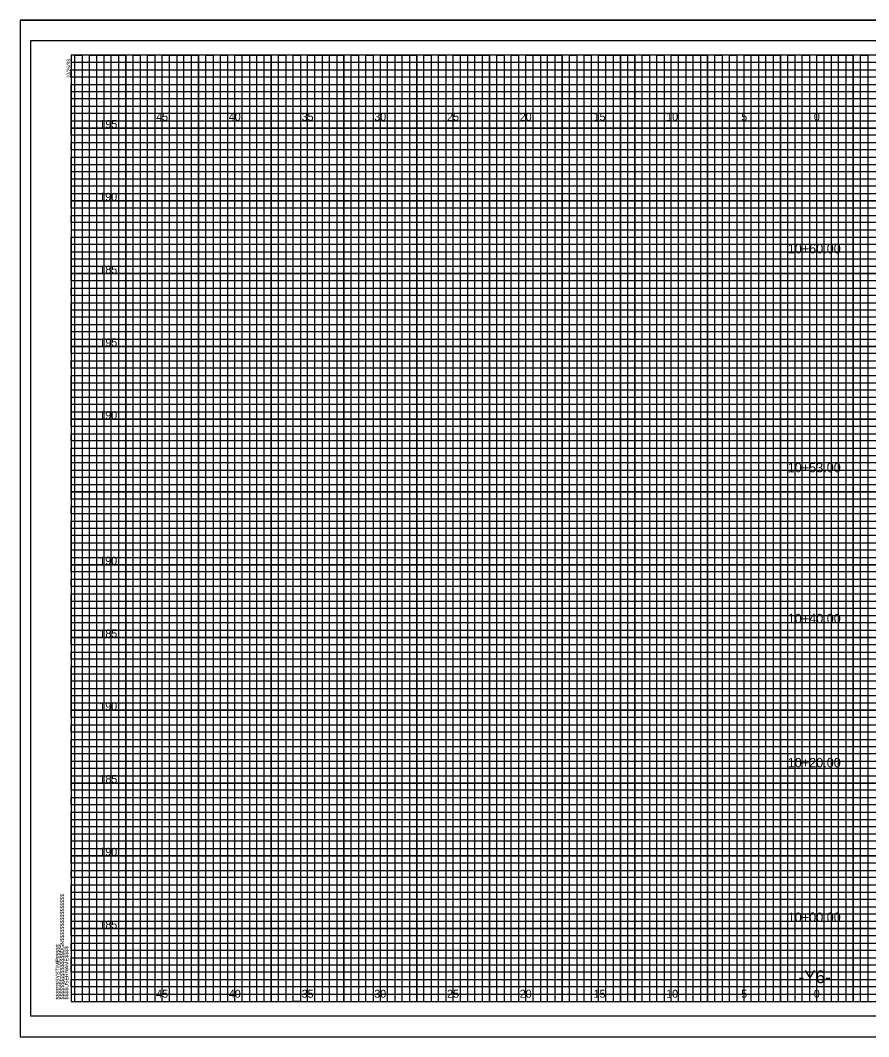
# Model space of a CAD drawing. Extents: x -4 to 103, y -2 to 138.
# Drawn here: x -3.5 to 54.8, y -2.4 to 67.4 of the extents above; entities that cross this region are included whole.
import ezdxf

# ---------------------------------------------------------------- set-up
doc = ezdxf.new("R2010")
doc.units = 0
for name, color, linetype in [('Old_Level_10', 7, 'Continuous'), ('Old_Level_16', 7, 'Continuous'), ('Old_Level_3', 7, 'Continuous'), ('Old_Level_4', 7, 'Continuous'), ('Old_Level_5', 7, 'Continuous'), ('Old_Level_8', 7, 'Continuous'), ('Prop Dimension', 7, 'Continuous'), ('Prop XS Dump Level', 7, 'Continuous'), ('Prop XS Finish Grade', 7, 'Continuous'), ('Prop XS SE Text', 7, 'Continuous'), ('Prop XS Subgrade Earthwork', 7, 'Continuous')]:
    doc.layers.add(name, color=color, linetype=linetype)

msp = doc.modelspace()

# ---------------------------------------------------------------- linework, layer by layer
at = {"layer": 'Old_Level_10'}
for p, q in [((1.25, 0), (1.25, 65)), ((3.75, 0), (3.75, 65)), ((6.25, 0), (6.25, 65)), ((8.75, 0), (8.75, 65)), ((11.25, 0), (11.25, 65)), ((13.75, 0), (13.75, 65)), ((16.25, 0), (16.25, 65)), ((18.75, 0), (18.75, 65)), ((21.25, 0), (21.25, 65)), ((23.75, 0), (23.75, 65)), ((26.25, 0), (26.25, 65)), ((28.75, 0), (28.75, 65)), ((31.25, 0), (31.25, 65)), ((33.75, 0), (33.75, 65)), ((36.25, 0), (36.25, 65)), ((38.75, 0), (38.75, 65)), ((41.25, 0), (41.25, 65)), ((43.75, 0), (43.75, 65)), ((46.25, 0), (46.25, 65)), ((48.75, 0), (48.75, 65)), ((51.25, 0), (51.25, 65)), ((53.75, 0), (53.75, 65)), ((0, 62.5), (74.25, 62.5)), ((0, 60), (102.5, 60)), ((0, 57.5), (102.5, 57.5)), ((0, 55), (102.5, 55)), ((0, 52.5), (102.5, 52.5)), ((0, 50), (102.5, 50)), ((0, 47.5), (102.5, 47.5)), ((0, 45), (102.5, 45)), ((0, 42.5), (102.5, 42.5)), ((0, 40), (102.5, 40)), ((0, 37.5), (102.5, 37.5)), ((0, 35), (102.5, 35)), ((0, 32.5), (102.5, 32.5)), ((0, 30), (102.5, 30)), ((0, 27.5), (102.5, 27.5)), ((0, 25), (102.5, 25)), ((0, 22.5), (102.5, 22.5)), ((0, 20), (102.5, 20)), ((0, 17.5), (102.5, 17.5)), ((0, 15), (102.5, 15)), ((0, 12.5), (102.5, 12.5)), ((0, 10), (102.5, 10)), ((0, 7.5), (102.5, 7.5)), ((0, 5), (102.5, 5)), ((0, 2.5), (102.5, 2.5))]:
    msp.add_line(p, q, dxfattribs=at)
at = {"layer": 'Old_Level_3'}
for p, q in [((-3.5, 67.4), (103.4, 67.4)), ((-3.5, 67.4), (-3.5, -2.425)), ((-3.5, -2.425), (102.1625, -2.425))]:
    msp.add_line(p, q, dxfattribs=at)
at = {"layer": 'Old_Level_4'}
msp.add_lwpolyline([(103, 66), (-2.8, 66), (-2.8, -1), (103, -1)], close=True, dxfattribs=at)
at = {"layer": 'Old_Level_5'}
msp.add_lwpolyline([(103.4, 67.4), (-3.5, 67.4), (-3.5, -2.425), (103.4, -2.425)], close=True, dxfattribs=at)
at = {"layer": 'Old_Level_8'}
for points in [[(1.25, 0), (1.25, 65), (3.75, 65), (3.75, 0), (6.25, 0), (6.25, 65), (8.75, 65), (8.75, 0), (11.25, 0), (11.25, 65), (13.75, 65), (13.75, 0), (16.25, 0), (16.25, 65), (18.75, 65), (18.75, 0), (21.25, 0), (21.25, 65), (23.75, 65), (23.75, 0), (26.25, 0), (26.25, 65), (28.75, 65), (28.75, 0), (31.25, 0), (31.25, 65), (33.75, 65), (33.75, 0), (36.25, 0), (36.25, 65), (38.75, 65), (38.75, 0), (41.25, 0), (41.25, 65), (43.75, 65), (43.75, 0), (46.25, 0), (46.25, 65), (48.75, 65), (48.75, 0), (51.25, 0), (51.25, 65), (53.75, 65), (53.75, 0)], [(102.5, 60), (0, 60), (0, 62.5), (74.25, 62.5)], [(102.5, 55), (0, 55), (0, 57.5), (102.5, 57.5)], [(102.5, 50), (0, 50), (0, 52.5), (102.5, 52.5)], [(102.5, 45), (0, 45), (0, 47.5), (102.5, 47.5)], [(102.5, 40), (0, 40), (0, 42.5), (102.5, 42.5)], [(102.5, 35), (0, 35), (0, 37.5), (102.5, 37.5)], [(102.5, 30), (0, 30), (0, 32.5), (102.5, 32.5)], [(102.5, 25), (0, 25), (0, 27.5), (102.5, 27.5)], [(102.5, 20), (0, 20), (0, 22.5), (102.5, 22.5)], [(102.5, 15), (0, 15), (0, 17.5), (102.5, 17.5)], [(102.5, 10), (0, 10), (0, 12.5), (102.5, 12.5)], [(102.5, 5), (0, 5), (0, 7.5), (102.5, 7.5)], [(0, 2.5), (102.5, 2.5)]]:
    msp.add_lwpolyline(points, dxfattribs=at)
at = {"layer": 'Prop Dimension'}
for points in [[(0.25, 0), (0.25, 65), (0.75, 65), (0.75, 0), (1.75, 0), (1.75, 65), (2.25, 65), (2.25, 0), (2.75, 0), (2.75, 65), (3.25, 65), (3.25, 0), (4.25, 0), (4.25, 65), (4.75, 65), (4.75, 0), (5.25, 0), (5.25, 65), (5.75, 65), (5.75, 0), (6.75, 0), (6.75, 65), (7.25, 65), (7.25, 0), (7.75, 0), (7.75, 65), (8.25, 65), (8.25, 0), (9.25, 0), (9.25, 65), (9.75, 65), (9.75, 0), (10.25, 0), (10.25, 65), (10.75, 65), (10.75, 0), (11.75, 0), (11.75, 65), (12.25, 65), (12.25, 0), (12.75, 0), (12.75, 65), (13.25, 65), (13.25, 0), (14.25, 0), (14.25, 65), (14.75, 65), (14.75, 0), (15.75, 0), (15.25, 0), (15.25, 65), (15.75, 65), (15.75, 0), (16.75, 0), (16.75, 65), (17.25, 65), (17.25, 0), (17.75, 0), (17.75, 65), (18.25, 65), (18.25, 0), (19.25, 0), (19.25, 65), (19.75, 65), (19.75, 0), (20.25, 0), (20.25, 65), (20.75, 65), (20.75, 0), (21.75, 0), (21.75, 65), (22.25, 65), (22.25, 0), (22.75, 0), (22.75, 65), (23.25, 65), (23.25, 0), (24.25, 0), (24.25, 65), (24.75, 65), (24.75, 0), (25.25, 0), (25.25, 65), (25.75, 65), (25.75, 0), (26.75, 0), (26.75, 65), (27.25, 65), (27.25, 0), (27.75, 0), (27.75, 65), (28.25, 65), (28.25, 0), (29.25, 0), (29.25, 65), (29.75, 65), (29.75, 0), (30.25, 0), (30.25, 65), (30.75, 65), (30.75, 0)], [(30.75, 0), (31.75, 0), (31.75, 65), (32.25, 65), (32.25, 0), (32.75, 0), (32.75, 65), (33.25, 65), (33.25, 0), (34.25, 0), (34.25, 65), (34.75, 65), (34.75, 0), (35.25, 0), (35.25, 65), (35.75, 65), (35.75, 0), (36.75, 0), (36.75, 65), (37.25, 65), (37.25, 0), (37.75, 0), (37.75, 65), (37.75, 0)], [(38.25, 65), (38.25, 0), (39.25, 0), (39.25, 65), (39.75, 65), (39.75, 0), (40.25, 0), (40.25, 65), (40.75, 65), (40.75, 0), (41.75, 0), (41.75, 65), (42.25, 65), (42.25, 0), (42.75, 0), (42.75, 65), (43.25, 65), (43.25, 0), (43.75, 0), (44.25, 0), (44.25, 65), (44.75, 65), (44.75, 0), (45.25, 0), (45.25, 65), (45.75, 65), (45.75, 0), (46.75, 0), (46.75, 65), (47.25, 65), (47.25, 0), (47.75, 0), (47.75, 65), (48.25, 65), (48.25, 0), (49.25, 0), (49.25, 65), (49.75, 65), (49.75, 0), (50.25, 0), (50.25, 65), (50.75, 65), (50.75, 0), (51.75, 0), (51.75, 65), (52.25, 65), (52.25, 0), (52.75, 0), (52.75, 65), (53.25, 65), (53.25, 0), (54.25, 0), (54.25, 65), (54.75, 65), (54.75, 0), (55.25, 0)], [(0, 62), (0, 63), (74.25, 63), (74.25, 63.5), (0, 63.5), (0, 64), (74.25, 64), (74.25, 64.5), (0, 64.5)], [(102.5, 62), (0, 62)], [(102.5, 61), (0, 61), (0, 61.5), (102.5, 61.5)], [(102.5, 59.5), (0, 59.5), (0, 60.5), (102.5, 60.5)], [(102.5, 58.5), (0, 58.5), (0, 59), (102.5, 59)], [(102.5, 57), (0, 57), (0, 58), (102.5, 58)], [(102.5, 56), (0, 56), (0, 56.5), (102.5, 56.5)], [(102.5, 54.5), (0, 54.5), (0, 55.5), (102.5, 55.5)], [(102.5, 53.5), (0, 53.5), (0, 54), (102.5, 54)], [(0, 53), (102.5, 53)], [(102.5, 52), (0, 52)], [(102.5, 51), (0, 51), (0, 51.5), (102.5, 51.5)], [(102.5, 49.5), (0, 49.5), (0, 50.5), (102.5, 50.5)], [(102.5, 48.5), (0, 48.5), (0, 49), (102.5, 49)], [(102.5, 47), (0, 47), (0, 48), (102.5, 48)], [(102.5, 46), (0, 46), (0, 46.5), (102.5, 46.5)], [(102.5, 44.5), (0, 44.5), (0, 45.5), (102.5, 45.5)], [(102.5, 43.5), (0, 43.5), (0, 44), (102.5, 44)], [(102.5, 42), (0, 42), (0, 43), (102.5, 43)], [(102.5, 41), (0, 41), (0, 41.5), (102.5, 41.5)], [(102.5, 39.5), (0, 39.5), (0, 40.5), (102.5, 40.5)], [(102.5, 38.5), (0, 38.5), (0, 39), (102.5, 39)], [(102.5, 37), (0, 37), (0, 38), (102.5, 38)], [(102.5, 36), (0, 36), (0, 36.5), (102.5, 36.5)], [(102.5, 34.5), (0, 34.5), (0, 35.5), (102.5, 35.5)], [(102.5, 33.5), (0, 33.5), (0, 34), (102.5, 34)], [(102.5, 32), (0, 32), (0, 33), (102.5, 33)], [(102.5, 31), (0, 31), (0, 31.5)], [(0, 31.5), (102.5, 31.5)], [(102.5, 29.5), (0, 29.5), (0, 30.5), (102.5, 30.5)], [(102.5, 28.5), (0, 28.5), (0, 29), (102.5, 29)], [(102.5, 27), (0, 27), (0, 28), (102.5, 28)], [(102.5, 26), (0, 26), (0, 26.5), (102.5, 26.5)], [(102.5, 24.5), (0, 24.5), (0, 25.5), (102.5, 25.5)], [(102.5, 23.5), (0, 23.5), (0, 24), (102.5, 24)], [(102.5, 22), (0, 22), (0, 23), (102.5, 23)], [(102.5, 21), (0, 21), (0, 21.5), (102.5, 21.5)], [(102.5, 19.5), (0, 19.5), (0, 20.5), (102.5, 20.5)], [(102.5, 18.5), (0, 18.5), (0, 19), (102.5, 19)], [(102.5, 17), (0, 17), (0, 18), (102.5, 18)], [(102.5, 16), (0, 16), (0, 16.5), (102.5, 16.5)], [(102.5, 14.5), (0, 14.5), (0, 15.5), (102.5, 15.5)], [(102.5, 13.5), (0, 13.5), (0, 14), (102.5, 14)], [(102.5, 12), (0, 12), (0, 13), (102.5, 13)], [(102.5, 11), (0, 11), (0, 11.5), (102.5, 11.5)], [(102.5, 9.5), (0, 9.5), (0, 10.5), (102.5, 10.5)], [(102.5, 8.5), (0, 8.5), (0, 9), (102.5, 9)], [(102.5, 7), (0, 7), (0, 8), (102.5, 8)], [(102.5, 6), (0, 6), (0, 6.5), (102.5, 6.5)], [(102.5, 4.5), (0, 4.5), (0, 5.5), (102.5, 5.5)], [(102.5, 3.5), (0, 3.5), (0, 4), (102.5, 4)], [(102.5, 2), (0, 2), (0, 3), (102.5, 3)], [(102.5, 1), (0, 1), (0, 1.5), (102.5, 1.5)], [(0, 0.5), (102.5, 0.5)]]:
    msp.add_lwpolyline(points, dxfattribs=at)
at = {"layer": 'Prop XS SE Text'}
for p, q in [((0, 0), (0, 0)), ((0, 0), (0, 0)), ((-3.5, -2.425), (103.4, -2.425))]:
    msp.add_line(p, q, dxfattribs=at)
msp.add_lwpolyline([(102.5, 65), (0, 65), (0, 0), (102.5, 0)], close=True, dxfattribs=at)

# ---------------------------------------------------------------- texts
at = {"layer": 'Old_Level_16'}
for s, p in [('45', (5.8399, 60.5)), ('40', (10.8313, 60.5)), ('35', (15.8399, 60.5)), ('30', (20.8313, 60.5)), ('25', (25.8399, 60.5)), ('20', (30.8313, 60.5)), ('15', (35.9058, 60.5)), ('10', (40.8971, 60.5)), ('5', (46.0574, 60.5)), ('0', (51.0488, 60.5)), ('0', (51.0488, 60.5)), ('45', (5.8399, 0.25)), ('40', (10.8313, 0.25)), ('35', (15.8399, 0.25)), ('30', (20.8313, 0.25)), ('25', (25.8399, 0.25)), ('20', (30.8313, 0.25)), ('15', (35.9058, 0.25)), ('10', (40.8971, 0.25)), ('5', (46.0574, 0.25)), ('0', (51.0488, 0.25)), ('0', (51.0488, 0.25))]:
    msp.add_text(s, height=0.55, dxfattribs=at).set_placement(p)
at = {"layer": 'Old_Level_8'}
msp.add_text('040397', height=0.0025, rotation=90, dxfattribs=at).set_placement((-0.0007, 64.9864))
at = {"layer": 'Prop XS Dump Level'}
msp.add_text('-Y6-', height=0.875, dxfattribs=at).set_placement((49.9985, 1.25))
at = {"layer": 'Prop XS Finish Grade'}
for s, p in [('195', (1.9383, 60)), ('190', (1.9296, 55)), ('185', (1.9383, 50)), ('195', (1.9383, 45)), ('190', (1.9296, 40)), ('190', (1.9296, 30)), ('185', (1.9383, 25)), ('190', (1.9296, 20)), ('185', (1.9383, 15)), ('190', (1.9296, 10)), ('185', (1.9383, 5))]:
    msp.add_text(s, height=0.55, dxfattribs=at).set_placement(p)
at = {"layer": 'Prop XS SE Text'}
for s, height, p in [('10/26/98', 0.25, (-0.0625, 63.4095)), ('$$$$$$$$$$$$$$$$DGN$$$$$$$$$$$$$$$$', 0.2625, (-0.5, 0.125)), ('$$$$$$SYSTIME$$$$$', 0.2625, (-0.7973, 0.1247)), ('$$$$USERNAME$$$$', 0.2625, (-0.2, 0.125))]:
    msp.add_text(s, height=height, rotation=90, dxfattribs=at).set_placement(p)
at = {"layer": 'Prop XS Subgrade Earthwork'}
for s, p in [('10+60.00', (49.2508, 51.3878)), ('10+53.00', (49.2508, 36.3488)), ('10+40.00', (49.2508, 25.976)), ('10+20.00', (49.2508, 16.0755)), ('10+00.00', (49.2508, 5.4542))]:
    msp.add_text(s, height=0.65, dxfattribs=at).set_placement(p)

doc.saveas('drawing.dxf')
